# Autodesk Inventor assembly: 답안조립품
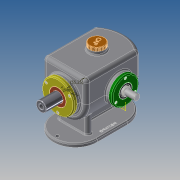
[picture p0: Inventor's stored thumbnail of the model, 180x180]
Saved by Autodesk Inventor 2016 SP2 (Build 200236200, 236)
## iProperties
Created: 2019-03
Part Number: 답안조립품
Document SubType Name: Assembly
Designer: EZ
Author: EZ
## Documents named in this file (16)
- X:\390307V1006 황수연\답안조립품.iam
- X:\390307V1006 황수연\본체.ipt
- X:\390307V1006 황수연\베어링 6205.ipt
- 베어링 6205.ipt
- X:\390307V1006 황수연\본체커버.ipt
- X:\390307V1006 황수연\볼트 M4.ipt
- X:\390307V1006 황수연\부시.ipt
- X:\390307V1006 황수연\상부 캡.ipt
- X:\390307V1006 황수연\슬라이드 커버.ipt
- X:\390307V1006 황수연\슬라이드.ipt
- X:\390307V1006 황수연\오일 실.ipt
- 오일 실.ipt
- X:\390307V1006 황수연\축 커버-1.ipt
- X:\390307V1006 황수연\축 커버-2.ipt
- X:\390307V1006 황수연\편심축.ipt
- X:\390307V1006 황수연\가변스프링.ipt
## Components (1 placed, 1 different names)
1. 가변스프링:1
